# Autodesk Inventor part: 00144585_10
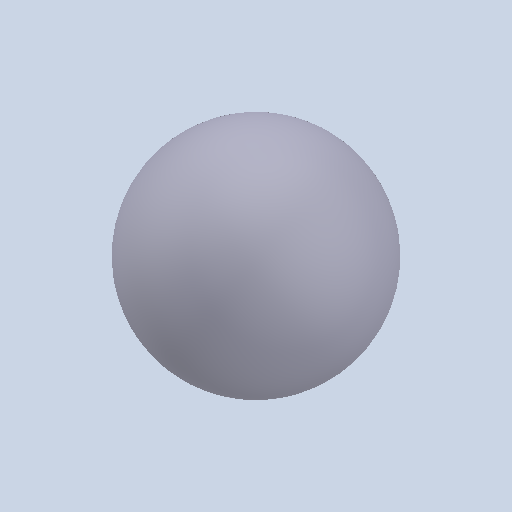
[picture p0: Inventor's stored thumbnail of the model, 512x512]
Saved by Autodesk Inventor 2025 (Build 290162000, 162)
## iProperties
Created: 2021-02
Part Number: 00144585_10
Material: Generico
Document SubType Name: Modeling
Designer: Ryzen5700u
Density: 1 g/cm^3
Appearance: Default
Author: Ryzen5700u
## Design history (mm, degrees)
feature "Solido1"
node "Solido2"
